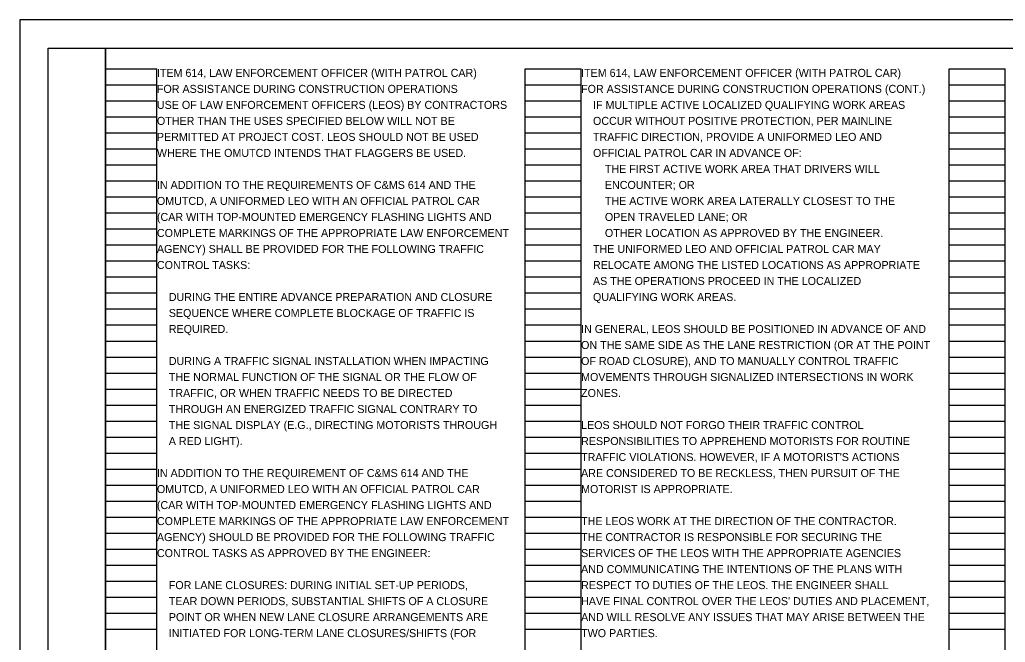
# Model space of a CAD drawing. Extents: x 0 to 34, y 0 to 22.
# Drawn here: x 0 to 17.24, y 11.11 to 22 of the extents above; entities that cross this region are included whole.
import ezdxf

# ---------------------------------------------------------------- set-up
doc = ezdxf.new("R2010")
doc.units = 0
for name, color, linetype in [('SH_Border', 7, 'Continuous'), ('SH_Cut_Line', 7, 'Continuous'), ('SH_Data', 7, 'Continuous'), ('SH_Text', 7, 'Continuous')]:
    doc.layers.add(name, color=color, linetype=linetype)

msp = doc.modelspace()

# ---------------------------------------------------------------- linework, layer by layer
at = {"layer": 'SH_Border'}
for points in [[(0.5, 21.5), (1.5, 21.5), (1.5, 0.5), (0.5, 0.5)], [(1.5, 21.5), (33.5, 21.5), (33.5, 0.5), (1.5, 0.5)]]:
    msp.add_lwpolyline(points, close=True, dxfattribs=at)
at = {"layer": 'SH_Cut_Line'}
msp.add_lwpolyline([(0, 0), (34, 0), (34, 22), (0, 22)], close=True, dxfattribs=at)
at = {"layer": 'SH_Data'}
for p, q in [((1.5, 0.98), (1.5, 21.14)), ((1.5, 21.14), (2.4, 21.14)), ((2.4, 0.98), (2.4, 21.14)), ((8.84, 0.98), (8.84, 21.14)), ((8.84, 21.14), (9.82, 21.14)), ((9.82, 0.98), (9.82, 21.14)), ((16.26, 0.98), (16.26, 21.14)), ((16.26, 21.14), (17.24, 21.14)), ((17.24, 0.98), (17.24, 21.14)), ((1.5, 20.86), (2.4, 20.86)), ((8.84, 20.86), (9.82, 20.86)), ((16.26, 20.86), (17.24, 20.86)), ((1.5, 20.58), (2.4, 20.58)), ((8.84, 20.58), (9.82, 20.58)), ((16.26, 20.58), (17.24, 20.58)), ((1.5, 20.3), (2.4, 20.3)), ((8.84, 20.3), (9.82, 20.3)), ((16.26, 20.3), (17.24, 20.3)), ((1.5, 20.02), (2.4, 20.02)), ((8.84, 20.02), (9.82, 20.02)), ((16.26, 20.02), (17.24, 20.02)), ((1.5, 19.74), (2.4, 19.74)), ((8.84, 19.74), (9.82, 19.74)), ((16.26, 19.74), (17.24, 19.74)), ((1.5, 19.46), (2.4, 19.46)), ((8.84, 19.46), (9.82, 19.46)), ((16.26, 19.46), (17.24, 19.46)), ((1.5, 19.18), (2.4, 19.18)), ((8.84, 19.18), (9.82, 19.18)), ((16.26, 19.18), (17.24, 19.18)), ((1.5, 18.9), (2.4, 18.9)), ((8.84, 18.9), (9.82, 18.9)), ((16.26, 18.9), (17.24, 18.9)), ((1.5, 18.62), (2.4, 18.62)), ((8.84, 18.62), (9.82, 18.62)), ((16.26, 18.62), (17.24, 18.62)), ((1.5, 18.34), (2.4, 18.34)), ((8.84, 18.34), (9.82, 18.34)), ((16.26, 18.34), (17.24, 18.34)), ((1.5, 18.06), (2.4, 18.06)), ((8.84, 18.06), (9.82, 18.06)), ((16.26, 18.06), (17.24, 18.06)), ((1.5, 17.78), (2.4, 17.78)), ((8.84, 17.78), (9.82, 17.78)), ((16.26, 17.78), (17.24, 17.78)), ((1.5, 17.5), (2.4, 17.5)), ((8.84, 17.5), (9.82, 17.5)), ((16.26, 17.5), (17.24, 17.5)), ((1.5, 17.22), (2.4, 17.22)), ((8.84, 17.22), (9.82, 17.22)), ((16.26, 17.22), (17.24, 17.22)), ((1.5, 16.94), (2.4, 16.94)), ((8.84, 16.94), (9.82, 16.94)), ((16.26, 16.94), (17.24, 16.94)), ((1.5, 16.66), (2.4, 16.66)), ((8.84, 16.66), (9.82, 16.66)), ((16.26, 16.66), (17.24, 16.66)), ((1.5, 16.38), (2.4, 16.38)), ((8.84, 16.38), (9.82, 16.38)), ((16.26, 16.38), (17.24, 16.38)), ((1.5, 16.1), (2.4, 16.1)), ((8.84, 16.1), (9.82, 16.1)), ((16.26, 16.1), (17.24, 16.1)), ((1.5, 15.82), (2.4, 15.82)), ((8.84, 15.82), (9.82, 15.82)), ((16.26, 15.82), (17.24, 15.82)), ((1.5, 15.54), (2.4, 15.54)), ((8.84, 15.54), (9.82, 15.54)), ((16.26, 15.54), (17.24, 15.54)), ((1.5, 15.26), (2.4, 15.26)), ((8.84, 15.26), (9.82, 15.26)), ((16.26, 15.26), (17.24, 15.26)), ((1.5, 14.98), (2.4, 14.98)), ((8.84, 14.98), (9.82, 14.98)), ((16.26, 14.98), (17.24, 14.98)), ((1.5, 14.7), (2.4, 14.7)), ((8.84, 14.7), (9.82, 14.7)), ((16.26, 14.7), (17.24, 14.7)), ((1.5, 14.42), (2.4, 14.42)), ((8.84, 14.42), (9.82, 14.42)), ((16.26, 14.42), (17.24, 14.42)), ((1.5, 14.14), (2.4, 14.14)), ((8.84, 14.14), (9.82, 14.14)), ((16.26, 14.14), (17.24, 14.14)), ((1.5, 13.86), (2.4, 13.86)), ((8.84, 13.86), (9.82, 13.86)), ((16.26, 13.86), (17.24, 13.86)), ((1.5, 13.58), (2.4, 13.58)), ((8.84, 13.58), (9.82, 13.58)), ((16.26, 13.58), (17.24, 13.58)), ((1.5, 13.3), (2.4, 13.3)), ((8.84, 13.3), (9.82, 13.3)), ((16.26, 13.3), (17.24, 13.3)), ((1.5, 13.02), (2.4, 13.02)), ((8.84, 13.02), (9.82, 13.02)), ((16.26, 13.02), (17.24, 13.02)), ((1.5, 12.74), (2.4, 12.74)), ((8.84, 12.74), (9.82, 12.74)), ((16.26, 12.74), (17.24, 12.74)), ((1.5, 12.46), (2.4, 12.46)), ((8.84, 12.46), (9.82, 12.46)), ((16.26, 12.46), (17.24, 12.46)), ((1.5, 12.18), (2.4, 12.18)), ((8.84, 12.18), (9.82, 12.18)), ((16.26, 12.18), (17.24, 12.18)), ((1.5, 11.9), (2.4, 11.9)), ((8.84, 11.9), (9.82, 11.9)), ((16.26, 11.9), (17.24, 11.9)), ((1.5, 11.62), (2.4, 11.62)), ((8.84, 11.62), (9.82, 11.62)), ((16.26, 11.62), (17.24, 11.62)), ((1.5, 11.34), (2.4, 11.34)), ((8.84, 11.34), (9.82, 11.34)), ((16.26, 11.34), (17.24, 11.34))]:
    msp.add_line(p, q, dxfattribs=at)

# ---------------------------------------------------------------- texts
at = {"layer": 'SH_Text'}
for s, p in [('ITEM 614, LAW ENFORCEMENT OFFICER (WITH PATROL CAR)', (2.4, 21)), ('ITEM 614, LAW ENFORCEMENT OFFICER (WITH PATROL CAR)', (9.82, 21)), ('FOR ASSISTANCE DURING CONSTRUCTION OPERATIONS', (2.4, 20.72)), ('FOR ASSISTANCE DURING CONSTRUCTION OPERATIONS (CONT.)', (9.82, 20.72)), ('USE OF LAW ENFORCEMENT OFFICERS (LEOS) BY CONTRACTORS', (2.4, 20.44)), ('    IF MULTIPLE ACTIVE LOCALIZED QUALIFYING WORK AREAS', (9.82, 20.44)), ('OTHER THAN THE USES SPECIFIED BELOW WILL NOT BE', (2.4, 20.16)), ('    OCCUR WITHOUT POSITIVE PROTECTION, PER MAINLINE', (9.82, 20.16)), ('PERMITTED AT PROJECT COST. LEOS SHOULD NOT BE USED', (2.4, 19.88)), ('    TRAFFIC DIRECTION, PROVIDE A UNIFORMED LEO AND', (9.82, 19.88)), ('WHERE THE OMUTCD INTENDS THAT FLAGGERS BE USED.', (2.4, 19.6)), ('    OFFICIAL PATROL CAR IN ADVANCE OF:', (9.82, 19.6)), ('        THE FIRST ACTIVE WORK AREA THAT DRIVERS WILL', (9.82, 19.32)), ('IN ADDITION TO THE REQUIREMENTS OF C&MS 614 AND THE', (2.4, 19.04)), ('        ENCOUNTER; OR', (9.82, 19.04)), ('OMUTCD, A UNIFORMED LEO WITH AN OFFICIAL PATROL CAR', (2.4, 18.76)), ('        THE ACTIVE WORK AREA LATERALLY CLOSEST TO THE', (9.82, 18.76)), ('(CAR WITH TOP-MOUNTED EMERGENCY FLASHING LIGHTS AND', (2.4, 18.48)), ('        OPEN TRAVELED LANE; OR', (9.82, 18.48)), ('COMPLETE MARKINGS OF THE APPROPRIATE LAW ENFORCEMENT', (2.4, 18.2)), ('        OTHER LOCATION AS APPROVED BY THE ENGINEER.', (9.82, 18.2)), ('AGENCY) SHALL BE PROVIDED FOR THE FOLLOWING TRAFFIC', (2.4, 17.92)), ('    THE UNIFORMED LEO AND OFFICIAL PATROL CAR MAY', (9.82, 17.92)), ('CONTROL TASKS:', (2.4, 17.64)), ('    RELOCATE AMONG THE LISTED LOCATIONS AS APPROPRIATE', (9.82, 17.64)), ('    AS THE OPERATIONS PROCEED IN THE LOCALIZED', (9.82, 17.36)), ('    DURING THE ENTIRE ADVANCE PREPARATION AND CLOSURE', (2.4, 17.08)), ('    QUALIFYING WORK AREAS.', (9.82, 17.08)), ('    SEQUENCE WHERE COMPLETE BLOCKAGE OF TRAFFIC IS', (2.4, 16.8)), ('    REQUIRED.', (2.4, 16.52)), ('IN GENERAL, LEOS SHOULD BE POSITIONED IN ADVANCE OF AND', (9.82, 16.52)), ('ON THE SAME SIDE AS THE LANE RESTRICTION (OR AT THE POINT', (9.82, 16.24)), ('    DURING A TRAFFIC SIGNAL INSTALLATION WHEN IMPACTING', (2.4, 15.96)), ('OF ROAD CLOSURE), AND TO MANUALLY CONTROL TRAFFIC', (9.82, 15.96)), ('    THE NORMAL FUNCTION OF THE SIGNAL OR THE FLOW OF', (2.4, 15.68)), ('MOVEMENTS THROUGH SIGNALIZED INTERSECTIONS IN WORK', (9.82, 15.68)), ('    TRAFFIC, OR WHEN TRAFFIC NEEDS TO BE DIRECTED', (2.4, 15.4)), ('ZONES.', (9.82, 15.4)), ('    THROUGH AN ENERGIZED TRAFFIC SIGNAL CONTRARY TO', (2.4, 15.12)), ('    THE SIGNAL DISPLAY (E.G., DIRECTING MOTORISTS THROUGH', (2.4, 14.84)), ('LEOS SHOULD NOT FORGO THEIR TRAFFIC CONTROL', (9.82, 14.84)), ('    A RED LIGHT).', (2.4, 14.56)), ('RESPONSIBILITIES TO APPREHEND MOTORISTS FOR ROUTINE', (9.82, 14.56)), ("TRAFFIC VIOLATIONS. HOWEVER, IF A MOTORIST'S ACTIONS", (9.82, 14.28)), ('IN ADDITION TO THE REQUIREMENT OF C&MS 614 AND THE', (2.4, 14)), ('ARE CONSIDERED TO BE RECKLESS, THEN PURSUIT OF THE', (9.82, 14)), ('OMUTCD, A UNIFORMED LEO WITH AN OFFICIAL PATROL CAR', (2.4, 13.72)), ('MOTORIST IS APPROPRIATE.', (9.82, 13.72)), ('(CAR WITH TOP-MOUNTED EMERGENCY FLASHING LIGHTS AND', (2.4, 13.44)), ('COMPLETE MARKINGS OF THE APPROPRIATE LAW ENFORCEMENT', (2.4, 13.16)), ('THE LEOS WORK AT THE DIRECTION OF THE CONTRACTOR.', (9.82, 13.16)), ('AGENCY) SHOULD BE PROVIDED FOR THE FOLLOWING TRAFFIC', (2.4, 12.88)), ('THE CONTRACTOR IS RESPONSIBLE FOR SECURING THE', (9.82, 12.88)), ('CONTROL TASKS AS APPROVED BY THE ENGINEER:', (2.4, 12.6)), ('SERVICES OF THE LEOS WITH THE APPROPRIATE AGENCIES', (9.82, 12.6)), ('AND COMMUNICATING THE INTENTIONS OF THE PLANS WITH', (9.82, 12.32)), ('    FOR LANE CLOSURES: DURING INITIAL SET-UP PERIODS,', (2.4, 12.04)), ('RESPECT TO DUTIES OF THE LEOS. THE ENGINEER SHALL', (9.82, 12.04)), ('    TEAR DOWN PERIODS, SUBSTANTIAL SHIFTS OF A CLOSURE', (2.4, 11.76)), ("HAVE FINAL CONTROL OVER THE LEOS' DUTIES AND PLACEMENT,", (9.82, 11.76)), ('    POINT OR WHEN NEW LANE CLOSURE ARRANGEMENTS ARE', (2.4, 11.48)), ('AND WILL RESOLVE ANY ISSUES THAT MAY ARISE BETWEEN THE', (9.82, 11.48)), ('    INITIATED FOR LONG-TERM LANE CLOSURES/SHIFTS (FOR', (2.4, 11.2)), ('TWO PARTIES.', (9.82, 11.2))]:
    msp.add_text(s, height=0.14, dxfattribs=at).set_placement(p)

doc.saveas('drawing.dxf')
